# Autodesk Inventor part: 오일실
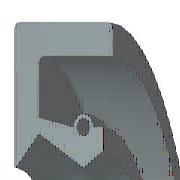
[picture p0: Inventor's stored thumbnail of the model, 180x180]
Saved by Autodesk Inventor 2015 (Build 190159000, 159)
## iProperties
IsCustomPart: 0
Created: 2014-10
Part Number: 오일실
Material: Rubber
Description: 오일-실
Document SubType Name: Modeling
Standard: KS B 2804
Designer: KYOUNG IL JANG
Standards Organization: KS
Language: ko-KR
Size Designation: D - 17 32 8
Categories: <MemberInstance><Categories><Category DisplayName="샤프트 부품" InternalName="7f7aeb1f-a693-4053-b835-cee3144e0d98" Mnemonic="SHFT"><Category DisplayName="실링" Intern
Density: 0.93 g/cm^3
Mass: 2.28027 g
Surface Area: 32.1224 cm^2
Volume: 2.45191 cm^3
Appearance: Rubber - Black - Version 1.1
Author: SeoGD™ [www.esajin.kr]
Revision Number: 1
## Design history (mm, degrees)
revolve "본체" stored, may be unused: angle "d17" = 90 deg
revolve "스프링1" stored, may be unused: angle "d18" = 90 deg
body "Solid1"
sketch "스케치1"
  geometry: L1 (0, 16)-(8, 16); L2 (8, 14.25)-(1.75, 14.25); L3 (1.75, 10.25)-(4.9, 8.5); L4 (4.9, 8.5)-(0, 8.5); L5 (0, 0)-(9.586, 0) reference; L6 (4.9, 8.5)-(6.3, 9.375); L7 (0, 18)-(0, -3) reference; L8 (-1.941, 0)-(11.507, 0) reference; L9 (4.2, 10.6)-(1.75, 11.21); L10 (1.75, 11.21)-(1.75, 14.25); L11 (0, 16)-(0, 8.588); L12 (4.9, 8.5)-(0, 8.5); L13 (1.75, 10.25)-(0.152, 8.528); L14 (8, 16)-(8, 14.25); L15 (5.6, 10.6)-(6.3, 10.6); L16 (6.3, 10.6)-(6.3, 9.375); C1 r 0.455 at (4.9, 10.6); A1 r 0.7 centre (4.9, 10.6) between (5.6, 10.6) and (4.2, 10.6); A2 r 0.088 centre (0.088, 8.588) between (0, 8.588) and (0.152, 8.528); 1 further point
  constraints: 28 end point, 5 horizontal alignment, 5 point on line, 4 point on circle, 4 vertical alignment, 3 centre point, 3 tangent, 2 collinear, 2 horizontal, 2 perpendicular, 1 coincident, 1 parallel
  dimensions: "d0" = 32 diameter of L1 L5 (= SD2); "d1" = 1.75 distance of L1.end L2.start (= SD); "d2" = 0.91 diameter of C1 (= SPDI); "d3" = 1.4 diameter of A1 (= SPDA); "d4" = 17 diameter of L3.end L5 (= NND); "d5" = 20.5 diameter of L3.start L5 (= TKDM); "d7" = 22.42 diameter of L9.end L5 (= TKDM + 0.24 x SWDT); "d8" = 1.75 distance between parallel lines of L11 L10 (= SD); "d9" = 4.9 distance from line of L11 C1.centre (= SPDST); "d10" = 21.2 diameter of C1.centre L5 (= HLDM); "d11" = 0.0875 radius of A2 (= 0.25 x LAB); "d12" = 6.3 distance between parallel lines of L11 L16 (= SDI); "d13" = 18.75 diameter of L6.end L5 (= ABDM); "d14" = 8 distance from line of L11 L1.end (= SWDT)
fillet "모깎기1" dims "d6" = 0.3 (= RR)
other parameters: "SD2" = 32 [user parameter; used in 1 equation term], "SWDT" = 8 [user parameter; used in 2 equation terms], "RR" = 0.3 [user parameter; used in 1 equation term], "SD" = 1.75 [user parameter; used in 2 equation terms], "NND" = 17 [user parameter; used in 1 equation term], "SPDA" = 1.4 [user parameter; used in 1 equation term], "SPDI" = 0.91 [user parameter; used in 1 equation term], "TKDM" = 20.5 [user parameter; used in 2 equation terms], "HLDM" = 21.2 [user parameter; used in 1 equation term], "ABDM" = 18.75 [user parameter; used in 1 equation term], "SDI" = 6.3 [user parameter; used in 1 equation term], "SPDST" = 4.9 [user parameter; used in 1 equation term], "LAB" = 0.35 [user parameter; used in 1 equation term], "d15" = 0, "d16" = 0, "d19" = 0
